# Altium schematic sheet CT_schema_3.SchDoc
size 321 x 189 mm
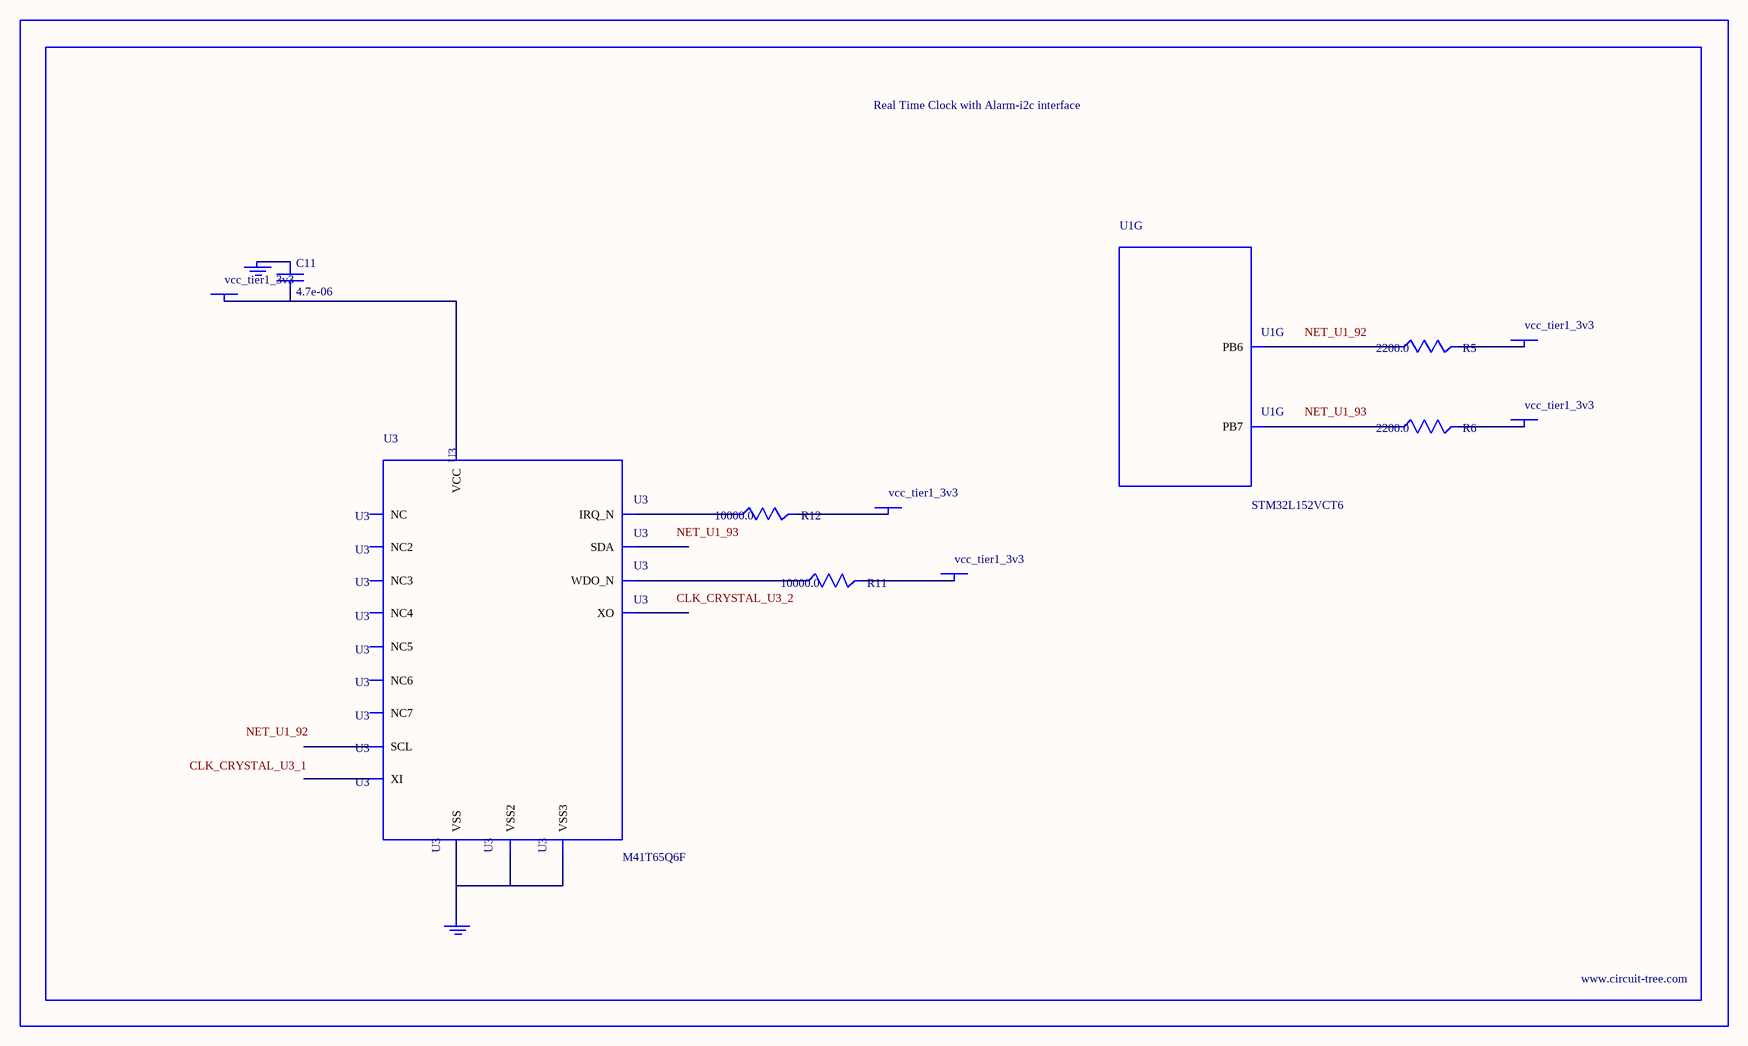
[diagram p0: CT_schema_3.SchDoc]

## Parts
BORDER2  (no value)
C11  4.7e-06  [C0805]
GND_INSTANCE_2_0  (no value)
GND_INSTANCE_2_1  (no value)
POWER_INSTANCE_2_0  vcc_tier1_3v3
POWER_INSTANCE_2_1  vcc_tier1_3v3
POWER_INSTANCE_2_2  vcc_tier1_3v3
POWER_INSTANCE_2_3  vcc_tier1_3v3
POWER_INSTANCE_2_4  vcc_tier1_3v3
R5  2200.0  [R0603]
R6  2200.0  [R0603]
R11  10000.0  [R0603]
R12  10000.0  [R0603]
U1  STM32L152VCT6  [LQFP100]  (part G of 9)
U3  M41T65Q6F  [M41T65_QFN-16]

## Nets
NetC11_1: C11.1 GND_INSTANCE_2_0.0(GND)
NetC11_2: C11.2 POWER_INSTANCE_2_2.0(PWR) U3.14(VCC)
NetGND_INSTANCE_2_1_0: GND_INSTANCE_2_1.0(GND) U3.3(VSS) U3.5(VSS2) U3.17(VSS3)
NetPOWER_INSTANCE_2_0_0: POWER_INSTANCE_2_0.0(PWR) R11.2
NetPOWER_INSTANCE_2_1_0: POWER_INSTANCE_2_1.0(PWR) R12.2
NetPOWER_INSTANCE_2_3_0: POWER_INSTANCE_2_3.0(PWR) R5.2
NetPOWER_INSTANCE_2_4_0: POWER_INSTANCE_2_4.0(PWR) R6.2
NetR5_1: R5.1 U1.92(PB6)
NetR6_1: R6.1 U1.93(PB7)
NetR11_1: R11.1 U3.4(WDO_N)
NetR12_1: R12.1 U3.11(IRQ_N)

Not connected (* = marked no-connect by the designer): U3 1(XI) 2(XO) 6(NC) 7(NC2) 8(NC3) 9(SDA) 10(SCL) 12(NC4) 13(NC5) 15(NC6) 16(NC7)

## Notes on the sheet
- Labels drawn without touching a wire or pin: CLK_CRYSTAL_U3_1, CLK_CRYSTAL_U3_2, NET_U1_92, NET_U1_93

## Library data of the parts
BORDER2 = BORDER_PAGE2
C11 = C0805C475K4RACTU
GND_INSTANCE_2_0 GND_INSTANCE_2_1 = GND
POWER_INSTANCE_2_0-POWER_INSTANCE_2_4 = PWR
R5 R6 = RC0603JR-072K2L
R11 R12 = RC0603JR-0710KL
